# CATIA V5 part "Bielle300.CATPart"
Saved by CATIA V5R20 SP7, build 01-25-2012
Part number: Bielle300
Publications: "Demi_longueur_bielle", "Rayon_bielle", "Diam_trou_ext", "Diam_trou_int", "Hauteur_Extremite"
Bounding box of the stored display mesh (mm): x -170 to 170, y -20 to 20, z -10 to 10
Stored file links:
  D:\thinkmotion-MPB\Fait\Mettre en ligne\CIAO_2010\CIAO_2010_544_thucteau\CAO\Bielle300.CATPart
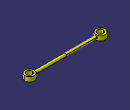
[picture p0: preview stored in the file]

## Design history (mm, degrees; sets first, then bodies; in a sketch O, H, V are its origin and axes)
Parameters
  Demi_longueur_bielle = 150 mm
  Rayon_bielle = 6 mm
  Diam_trou_ext = 40 mm
  Diam_trou_int = 25 mm {= (Diam_trou_ext+10mm) /2}
  Hauteur_Extremite = 10 mm
Body1 (main body)
  Sketch1 on xy-plane, origin (0, 0, 0), H (1, 0, 0), V (0, 1, 0)
    point P1 (-150, 0)
    line L1 (-150, 0) -> (-150, 6)
    line L2 (-150, 6) -> (0, 6)
    line L3 (0, 6) -> (0, 0)
    line L4 (0, 0) -> (-150, 0)
    length L2 = 150 {= Demi_longueur_bielle}
    length L1 = 6 {= Rayon_bielle}
    coincidence: P1 H, L3 V
    vertical: L1 V, L3 V
    horizontal: L2 H, L4 H
  Shaft1: profile Sketch1, axis Sketch1.L4, angle 360
  Sketch2 on xy-plane, origin (0, 0, 0), H (1, 0, 0), V (0, 1, 0)
    circle A1 centre (-150, 0) radius 20
    point P1 (-150, 0)
    reference projected line E1 (-150, 10) -> (-150, -10) from edge [face of Shaft1 from Sketch1.L1 | face of Shaft1 from Sketch1.L2]
    radius A1 = 20 {= Diam_trou_ext /2}
    coincidence: P1 H, P1 E1
  Pad1: profile Sketch2, direction (0, 0, 1), length 10 {= Hauteur_Extremite}, mirrored extent
  Sketch3 on end face of Pad1, origin (0, 0, 10), H (1, 0, 0), V (0, 1, 0)
    circle A1 centre (-150, 0) radius 12.5
    point P1 (-150, 0)
    reference projected circle E1 centre (-150, 0) radius 20 from edge [face of Pad1 from Sketch2.A1 | end face of Pad1]
    radius A1 = 12.5 {= Diam_trou_int /2}
    coincidence: P1 H
    concentricity: A1 E1
  Pocket1: profile Sketch3, direction (0, 0, -1), through (limit type 6)
  Mirror1: of Shaft1, Sketch1, Pad1, Sketch2, Pocket1, Sketch3, about yz-plane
